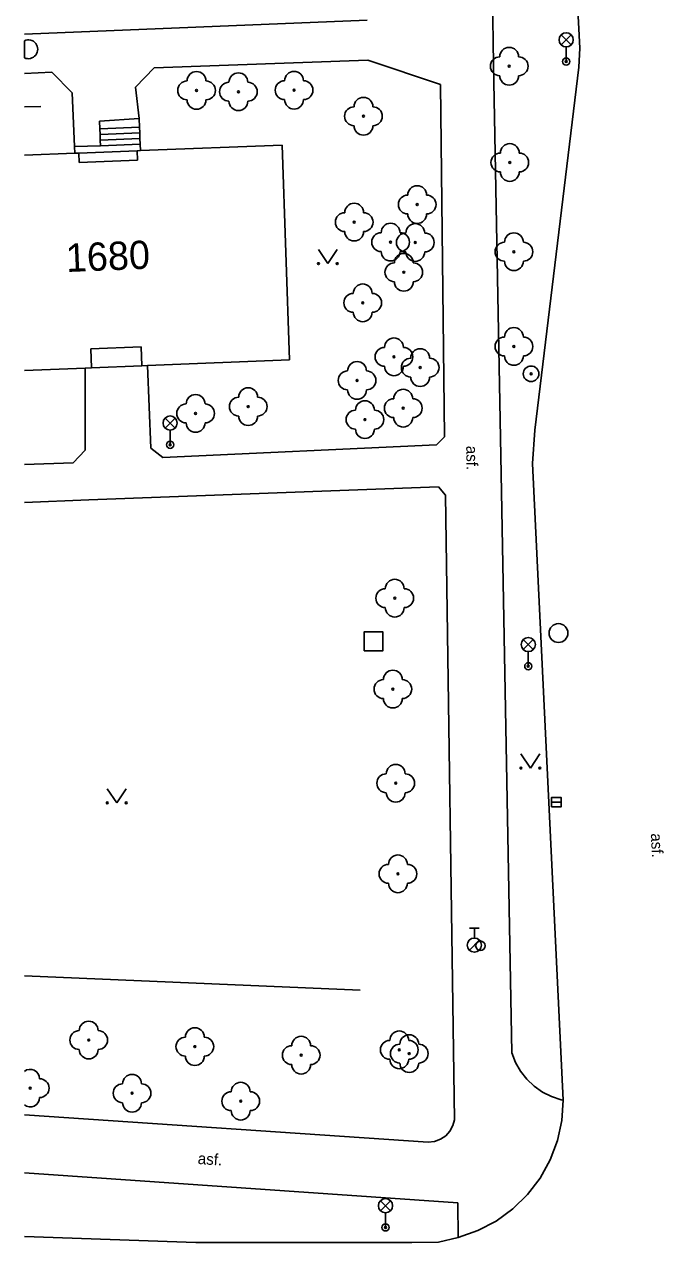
# Model space of a CAD drawing. Extents: x -640201 to -639641, y -1044739 to -1044317.
# Drawn here: x -640198.6 to -640164.7, y -1044618.4 to -1044553.9 of the extents above; entities that cross this region are included whole.
import ezdxf

# ---------------------------------------------------------------- set-up
doc = ezdxf.new("R2010")
doc.units = 0
for name, color, linetype in [('Budovy', 7, 'Continuous'), ('Ploty', 7, 'Continuous'), ('Pol_bod_pole', 7, 'Continuous'), ('Popis povrchů', 7, 'Continuous'), ('Popis ČP_ ČE', 7, 'Continuous'), ('Rozhraní ploch 1', 7, 'Continuous'), ('Rozhraní ploch 2', 7, 'Continuous'), ('Zeleň - stromy', 7, 'Continuous'), ('Znaky doprava', 7, 'Continuous'), ('Znaky kanalizace', 7, 'Continuous'), ('Znaky voda', 7, 'Continuous'), ('Značky KM', 7, 'Continuous'), ('Šachty ner_', 7, 'Continuous')]:
    doc.layers.add(name, color=color, linetype=linetype)

msp = doc.modelspace()

# ---------------------------------------------------------------- linework, layer by layer
at = {"layer": 'Budovy'}
for p, q in [((-640184.88, -1044560.28), (-640192.394, -1044560.573)), ((-640184.88, -1044560.28), (-640184.49, -1044571.66)), ((-640195.876, -1044560.709), (-640198.551, -1044560.817)), ((-640195.66, -1044560.7), (-640195.876, -1044560.709)), ((-640192.57, -1044560.58), (-640195.66, -1044560.7)), ((-640195.66, -1044560.7), (-640195.641, -1044561.2)), ((-640192.394, -1044560.573), (-640192.57, -1044560.58)), ((-640192.551, -1044561.08), (-640192.57, -1044560.58)), ((-640192.551, -1044561.08), (-640195.641, -1044561.2)), ((-640192.361, -1044570.971), (-640195.031, -1044571.081)), ((-640195.031, -1044571.081), (-640194.99, -1044572.08)), ((-640192.32, -1044571.97), (-640192.361, -1044570.971)), ((-640192.32, -1044571.97), (-640194.99, -1044572.08)), ((-640192.32, -1044571.97), (-640192.023, -1044571.958)), ((-640192.023, -1044571.958), (-640184.49, -1044571.66)), ((-640195.33, -1044572.094), (-640198.551, -1044572.222)), ((-640194.99, -1044572.08), (-640195.33, -1044572.094))]:
    msp.add_line(p, q, dxfattribs=at)
at = {"layer": 'Ploty'}
for p, q in [((-640198.551, -1044558.257), (-640197.67, -1044558.23)), ((-640180.75, -1044605.06), (-640198.551, -1044604.306))]:
    msp.add_line(p, q, dxfattribs=at)
at = {"layer": 'Pol_bod_pole'}
for radius in [0.412, 0.05]:
    msp.add_circle((-640171.68, -1044572.4), radius, dxfattribs=at)
at = {"layer": 'Rozhraní ploch 1'}
for p, q in [((-640173.68, -1044555.99), (-640174.11, -1044519.25)), ((-640170.63, -1044524.76), (-640169.09, -1044555.14)), ((-640180.38, -1044553.66), (-640198.551, -1044554.395)), ((-640169.09, -1044555.14), (-640169.14, -1044556.15)), ((-640180.33, -1044555.77), (-640191.67, -1044556.19)), ((-640180.33, -1044555.77), (-640176.49, -1044557.07)), ((-640197.09, -1044556.42), (-640198.551, -1044556.48)), ((-640196.02, -1044557.5), (-640197.09, -1044556.42)), ((-640191.67, -1044556.19), (-640192.65, -1044557.21)), ((-640173.68, -1044555.99), (-640173.31, -1044575.79)), ((-640169.14, -1044556.15), (-640171.48, -1044575.39)), ((-640176.28, -1044575.74), (-640176.49, -1044557.07)), ((-640195.89, -1044560.35), (-640196.02, -1044557.5)), ((-640192.65, -1044557.21), (-640192.46, -1044558.87)), ((-640192.023, -1044571.958), (-640191.85, -1044576.34)), ((-640195.33, -1044576.44), (-640195.33, -1044572.094)), ((-640176.69, -1044576.16), (-640176.28, -1044575.74)), ((-640173.31, -1044575.79), (-640172.7, -1044608.39)), ((-640171.48, -1044575.39), (-640171.6, -1044577.16)), ((-640195.97, -1044577.11), (-640195.33, -1044576.44)), ((-640191.85, -1044576.34), (-640191.2, -1044576.83)), ((-640191.2, -1044576.83), (-640176.69, -1044576.16)), ((-640198.551, -1044577.202), (-640195.97, -1044577.11)), ((-640171.6, -1044577.16), (-640169.98, -1044610.9)), ((-640195.13, -1044579.08), (-640176.59, -1044578.39)), ((-640176.59, -1044578.39), (-640176.22, -1044578.83)), ((-640198.551, -1044579.215), (-640195.13, -1044579.08)), ((-640175.74, -1044611.93), (-640176.22, -1044578.83)), ((-640177.13, -1044613.12), (-640198.551, -1044611.682)), ((-640175.56, -1044616.34), (-640198.551, -1044614.744)), ((-640175.54, -1044618.17), (-640175.56, -1044616.34)), ((-640198.551, -1044618.114), (-640189.458, -1044618.438)), ((-640189.458, -1044618.438), (-640178.008, -1044618.447)), ((-640178.008, -1044618.447), (-640176.59, -1044618.42)), ((-640175.54, -1044618.17), (-640176.59, -1044618.42))]:
    msp.add_line(p, q, dxfattribs=at)
for points in [[(-640172.7, -1044608.39), (-640172.508, -1044608.893), (-640172.243, -1044609.362), (-640171.912, -1044609.787), (-640171.522, -1044610.158), (-640171.081, -1044610.468), (-640170.599, -1044610.709), (-640170.087, -1044610.876), (-640169.98, -1044610.9)], [(-640175.54, -1044618.17), (-640174.506, -1044617.809), (-640173.535, -1044617.302), (-640172.648, -1044616.659), (-640171.865, -1044615.894), (-640171.201, -1044615.022), (-640170.671, -1044614.064), (-640170.285, -1044613.039), (-640170.054, -1044611.968), (-640169.98, -1044610.9)], [(-640177.13, -1044613.12), (-640176.798, -1044613.081), (-640176.485, -1044612.965), (-640176.21, -1044612.78), (-640175.983, -1044612.531), (-640175.823, -1044612.237), (-640175.74, -1044611.93)]]:
    msp.add_lwpolyline(points, dxfattribs=at)
at = {"layer": 'Rozhraní ploch 2'}
for p, q in [((-640192.46, -1044558.87), (-640194.56, -1044559.01)), ((-640192.442, -1044559.329), (-640194.548, -1044559.411)), ((-640192.43, -1044559.628), (-640194.539, -1044559.71)), ((-640194.52, -1044560.31), (-640195.89, -1044560.35)), ((-640195.876, -1044560.709), (-640195.89, -1044560.35)), ((-640192.419, -1044559.928), (-640194.53, -1044560.01)), ((-640192.407, -1044560.228), (-640194.52, -1044560.31))]:
    msp.add_line(p, q, dxfattribs=at)
for points in [[(-640194.56, -1044559.01), (-640194.548, -1044559.411), (-640194.539, -1044559.71), (-640194.53, -1044560.01), (-640194.52, -1044560.31)], [(-640192.394, -1044560.573), (-640192.407, -1044560.228), (-640192.419, -1044559.928), (-640192.43, -1044559.628), (-640192.442, -1044559.329), (-640192.46, -1044558.87)]]:
    msp.add_lwpolyline(points, dxfattribs=at)
at = {"layer": 'Zeleň - stromy'}
for centre in [(-640172.84, -1044556.1), (-640189.42, -1044557.38), (-640187.2, -1044557.45), (-640184.25, -1044557.37), (-640180.57, -1044558.75), (-640172.81, -1044561.2), (-640177.72, -1044563.43), (-640181.06, -1044564.36), (-640179.13, -1044565.42), (-640177.82, -1044565.44), (-640172.59, -1044565.93), (-640178.43, -1044567.02), (-640180.61, -1044568.64), (-640172.59, -1044570.95), (-640178.95, -1044571.5), (-640177.56, -1044572.07), (-640180.91, -1044572.75), (-640189.47, -1044574.5), (-640186.68, -1044574.14), (-640178.46, -1044574.22), (-640180.49, -1044574.83), (-640178.91, -1044584.29), (-640179.01, -1044589.11), (-640178.86, -1044594.1), (-640178.74, -1044598.9), (-640195.14, -1044607.71), (-640189.51, -1044608.06), (-640178.67, -1044608.23), (-640183.87, -1044608.51), (-640178.14, -1044608.43), (-640198.24, -1044610.26), (-640192.84, -1044610.53), (-640187.08, -1044610.95)]:
    msp.add_circle(centre, 0.05, dxfattribs=at)
for centre, start, end in [((-640172.84, -1044555.6), 0, 180), ((-640173.34, -1044556.1), 90, 270), ((-640172.34, -1044556.1), 270, 90), ((-640189.42, -1044556.88), 0, 180), ((-640187.2, -1044556.95), 0, 180), ((-640184.25, -1044556.87), 0, 180), ((-640189.92, -1044557.38), 90, 270), ((-640188.92, -1044557.38), 270, 90), ((-640187.7, -1044557.45), 90, 270), ((-640186.7, -1044557.45), 270, 90), ((-640184.75, -1044557.37), 90, 270), ((-640183.75, -1044557.37), 270, 90), ((-640172.84, -1044556.6), 180, 0), ((-640180.57, -1044558.25), 0, 180), ((-640189.42, -1044557.88), 180, 0), ((-640187.2, -1044557.95), 180, 0), ((-640184.25, -1044557.87), 180, 0), ((-640181.07, -1044558.75), 90, 270), ((-640180.07, -1044558.75), 270, 90), ((-640180.57, -1044559.25), 180, 0), ((-640172.81, -1044560.7), 0, 180), ((-640173.31, -1044561.2), 90, 270), ((-640172.31, -1044561.2), 270, 90), ((-640172.81, -1044561.7), 180, 0), ((-640178.22, -1044563.43), 90, 270), ((-640177.72, -1044562.93), 0, 180), ((-640177.22, -1044563.43), 270, 90), ((-640181.06, -1044563.86), 0, 180), ((-640181.56, -1044564.36), 90, 270), ((-640180.56, -1044564.36), 270, 90), ((-640177.72, -1044563.93), 180, 0), ((-640181.06, -1044564.86), 180, 0), ((-640179.63, -1044565.42), 90, 270), ((-640179.13, -1044564.92), 0, 180), ((-640178.63, -1044565.42), 270, 90), ((-640177.82, -1044564.94), 0, 180), ((-640178.32, -1044565.44), 90, 270), ((-640177.32, -1044565.44), 270, 90), ((-640173.09, -1044565.93), 90, 270), ((-640172.59, -1044565.43), 0, 180), ((-640172.09, -1044565.93), 270, 90), ((-640179.13, -1044565.92), 180, 0), ((-640178.43, -1044566.52), 0, 180), ((-640177.82, -1044565.94), 180, 0), ((-640178.93, -1044567.02), 90, 270), ((-640177.93, -1044567.02), 270, 90), ((-640172.59, -1044566.43), 180, 0), ((-640181.11, -1044568.64), 90, 270), ((-640180.61, -1044568.14), 0, 180), ((-640180.11, -1044568.64), 270, 90), ((-640178.43, -1044567.52), 180, 0), ((-640180.61, -1044569.14), 180, 0), ((-640172.59, -1044570.45), 0, 180), ((-640178.95, -1044571), 0, 180), ((-640173.09, -1044570.95), 90, 270), ((-640172.09, -1044570.95), 270, 90), ((-640179.45, -1044571.5), 90, 270), ((-640178.45, -1044571.5), 270, 90), ((-640177.56, -1044571.57), 0, 180), ((-640180.91, -1044572.25), 0, 180), ((-640178.95, -1044572), 180, 0), ((-640178.06, -1044572.07), 90, 270), ((-640177.06, -1044572.07), 270, 90), ((-640172.59, -1044571.45), 180, 0), ((-640181.41, -1044572.75), 90, 270), ((-640180.41, -1044572.75), 270, 90), ((-640177.56, -1044572.57), 180, 0), ((-640186.68, -1044573.64), 0, 180), ((-640180.91, -1044573.25), 180, 0), ((-640178.46, -1044573.72), 0, 180), ((-640189.47, -1044574), 0, 180), ((-640187.18, -1044574.14), 90, 270), ((-640186.18, -1044574.14), 270, 90), ((-640180.49, -1044574.33), 0, 180), ((-640178.96, -1044574.22), 90, 270), ((-640177.96, -1044574.22), 270, 90), ((-640189.97, -1044574.5), 90, 270), ((-640188.97, -1044574.5), 270, 90), ((-640180.99, -1044574.83), 90, 270), ((-640179.99, -1044574.83), 270, 90), ((-640189.47, -1044575), 180, 0), ((-640186.68, -1044574.64), 180, 0), ((-640178.46, -1044574.72), 180, 0), ((-640180.49, -1044575.33), 180, 0), ((-640178.91, -1044583.79), 0, 180), ((-640179.41, -1044584.29), 90, 270), ((-640178.41, -1044584.29), 270, 90), ((-640178.91, -1044584.79), 180, 0), ((-640179.01, -1044588.61), 0, 180), ((-640179.51, -1044589.11), 90, 270), ((-640178.51, -1044589.11), 270, 90), ((-640179.01, -1044589.61), 180, 0), ((-640178.86, -1044593.6), 0, 180), ((-640179.36, -1044594.1), 90, 270), ((-640178.36, -1044594.1), 270, 90), ((-640178.86, -1044594.6), 180, 0), ((-640179.24, -1044598.9), 90, 270), ((-640178.74, -1044598.4), 0, 180), ((-640178.24, -1044598.9), 270, 90), ((-640178.74, -1044599.4), 180, 0), ((-640195.14, -1044607.21), 0, 180), ((-640195.64, -1044607.71), 90, 270), ((-640194.64, -1044607.71), 270, 90), ((-640189.51, -1044607.56), 0, 180), ((-640183.87, -1044608.01), 0, 180), ((-640178.67, -1044607.73), 0, 180), ((-640178.14, -1044607.93), 0, 180), ((-640190.01, -1044608.06), 90, 270), ((-640189.01, -1044608.06), 270, 90), ((-640184.37, -1044608.51), 90, 270), ((-640183.37, -1044608.51), 270, 90), ((-640179.17, -1044608.23), 90, 270), ((-640178.64, -1044608.43), 90, 270), ((-640178.17, -1044608.23), 270, 90), ((-640177.64, -1044608.43), 270, 90), ((-640195.14, -1044608.21), 180, 0), ((-640189.51, -1044608.56), 180, 0), ((-640178.67, -1044608.73), 180, 0), ((-640198.24, -1044609.76), 0, 128.48476), ((-640183.87, -1044609.01), 180, 0), ((-640178.14, -1044608.93), 180, 0), ((-640197.74, -1044610.26), 270, 90), ((-640193.34, -1044610.53), 90, 270), ((-640192.84, -1044610.03), 0, 180), ((-640192.34, -1044610.53), 270, 90), ((-640187.08, -1044610.45), 0, 180), ((-640198.24, -1044610.76), 231.51524, 0), ((-640187.58, -1044610.95), 90, 270), ((-640186.58, -1044610.95), 270, 90), ((-640192.84, -1044611.03), 180, 0), ((-640187.08, -1044611.45), 180, 0)]:
    msp.add_arc(centre, 0.5, start, end, dxfattribs=at)
at = {"layer": 'Znaky doprava'}
for p, q in [((-640170.085, -1044554.435), (-640169.555, -1044554.965)), ((-640170.085, -1044554.965), (-640169.555, -1044554.435)), ((-640169.82, -1044555.85), (-640169.82, -1044555.075)), ((-640191.085, -1044574.745), (-640190.555, -1044575.275)), ((-640191.085, -1044575.275), (-640190.555, -1044574.745)), ((-640190.82, -1044576.16), (-640190.82, -1044575.385)), ((-640172.095, -1044586.485), (-640171.565, -1044587.015)), ((-640172.095, -1044587.015), (-640171.565, -1044586.485)), ((-640171.83, -1044587.9), (-640171.83, -1044587.125)), ((-640179.665, -1044616.225), (-640179.135, -1044616.755)), ((-640179.665, -1044616.755), (-640179.135, -1044616.225)), ((-640179.4, -1044617.64), (-640179.4, -1044616.865))]:
    msp.add_line(p, q, dxfattribs=at)
for centre, radius in [((-640169.82, -1044554.7), 0.375), ((-640169.82, -1044555.85), 0.19), ((-640169.82, -1044555.85), 0.05), ((-640190.82, -1044575.01), 0.375), ((-640190.82, -1044576.16), 0.19), ((-640190.82, -1044576.16), 0.05), ((-640171.83, -1044586.75), 0.375), ((-640171.83, -1044587.9), 0.19), ((-640171.83, -1044587.9), 0.05), ((-640179.4, -1044616.49), 0.375), ((-640179.4, -1044617.64), 0.19), ((-640179.4, -1044617.64), 0.05)]:
    msp.add_circle(centre, radius, dxfattribs=at)
at = {"layer": 'Znaky kanalizace'}
msp.add_line((-640170.59, -1044595.1), (-640170.09, -1044595.1), dxfattribs=at)
msp.add_lwpolyline([(-640198.551, -1044554.747), (-640198.551, -1044555.653)], dxfattribs=at)
msp.add_lwpolyline([(-640170.59, -1044595.35), (-640170.09, -1044595.35), (-640170.09, -1044594.85), (-640170.59, -1044594.85)], close=True, dxfattribs=at)
msp.add_circle((-640170.23, -1044586.14), 0.5, dxfattribs=at)
msp.add_arc((-640198.34, -1044555.2), 0.5, 245.01971, 114.98029, dxfattribs=at)
at = {"layer": 'Znaky voda'}
for p, q in [((-640174.94, -1044601.78), (-640174.44, -1044601.78)), ((-640174.69, -1044602.305), (-640174.69, -1044601.78)), ((-640174.955, -1044602.945), (-640174.425, -1044602.415))]:
    msp.add_line(p, q, dxfattribs=at)
for centre, radius in [((-640174.69, -1044602.68), 0.375), ((-640174.37, -1044602.71), 0.25)]:
    msp.add_circle(centre, radius, dxfattribs=at)
at = {"layer": 'Značky KM'}
for p, q in [((-640182.959, -1044565.81), (-640182.459, -1044566.56)), ((-640182.459, -1044566.56), (-640181.959, -1044565.81)), ((-640172.217, -1044592.542), (-640171.717, -1044593.292)), ((-640171.717, -1044593.292), (-640171.217, -1044592.542)), ((-640194.152, -1044594.39), (-640193.652, -1044595.14)), ((-640193.652, -1044595.14), (-640193.152, -1044594.39))]:
    msp.add_line(p, q, dxfattribs=at)
for centre in [(-640182.959, -1044566.56), (-640181.959, -1044566.56), (-640172.217, -1044593.292), (-640171.217, -1044593.292), (-640194.152, -1044595.14), (-640193.152, -1044595.14)]:
    msp.add_circle(centre, 0.05, dxfattribs=at)
at = {"layer": 'Šachty ner_'}
msp.add_lwpolyline([(-640180.54, -1044587.08), (-640179.54, -1044587.08), (-640179.54, -1044586.08), (-640180.54, -1044586.08)], close=True, dxfattribs=at)

# ---------------------------------------------------------------- texts
at = {"layer": 'Popis povrchů'}
for rotation, p in [(270.83082, (-640175.12, -1044576.217)), (272.7489, (-640165.332, -1044596.765)), (356.0287, (-640189.369, -1044614.276))]:
    msp.add_text('asf.', height=0.6, rotation=rotation, dxfattribs=at).set_placement(p)
at = {"layer": 'Popis ČP_ ČE'}
msp.add_text('1680', height=1.5, rotation=2.35917, dxfattribs=at).set_placement((-640196.322, -1044567.008))

doc.saveas('drawing.dxf')
